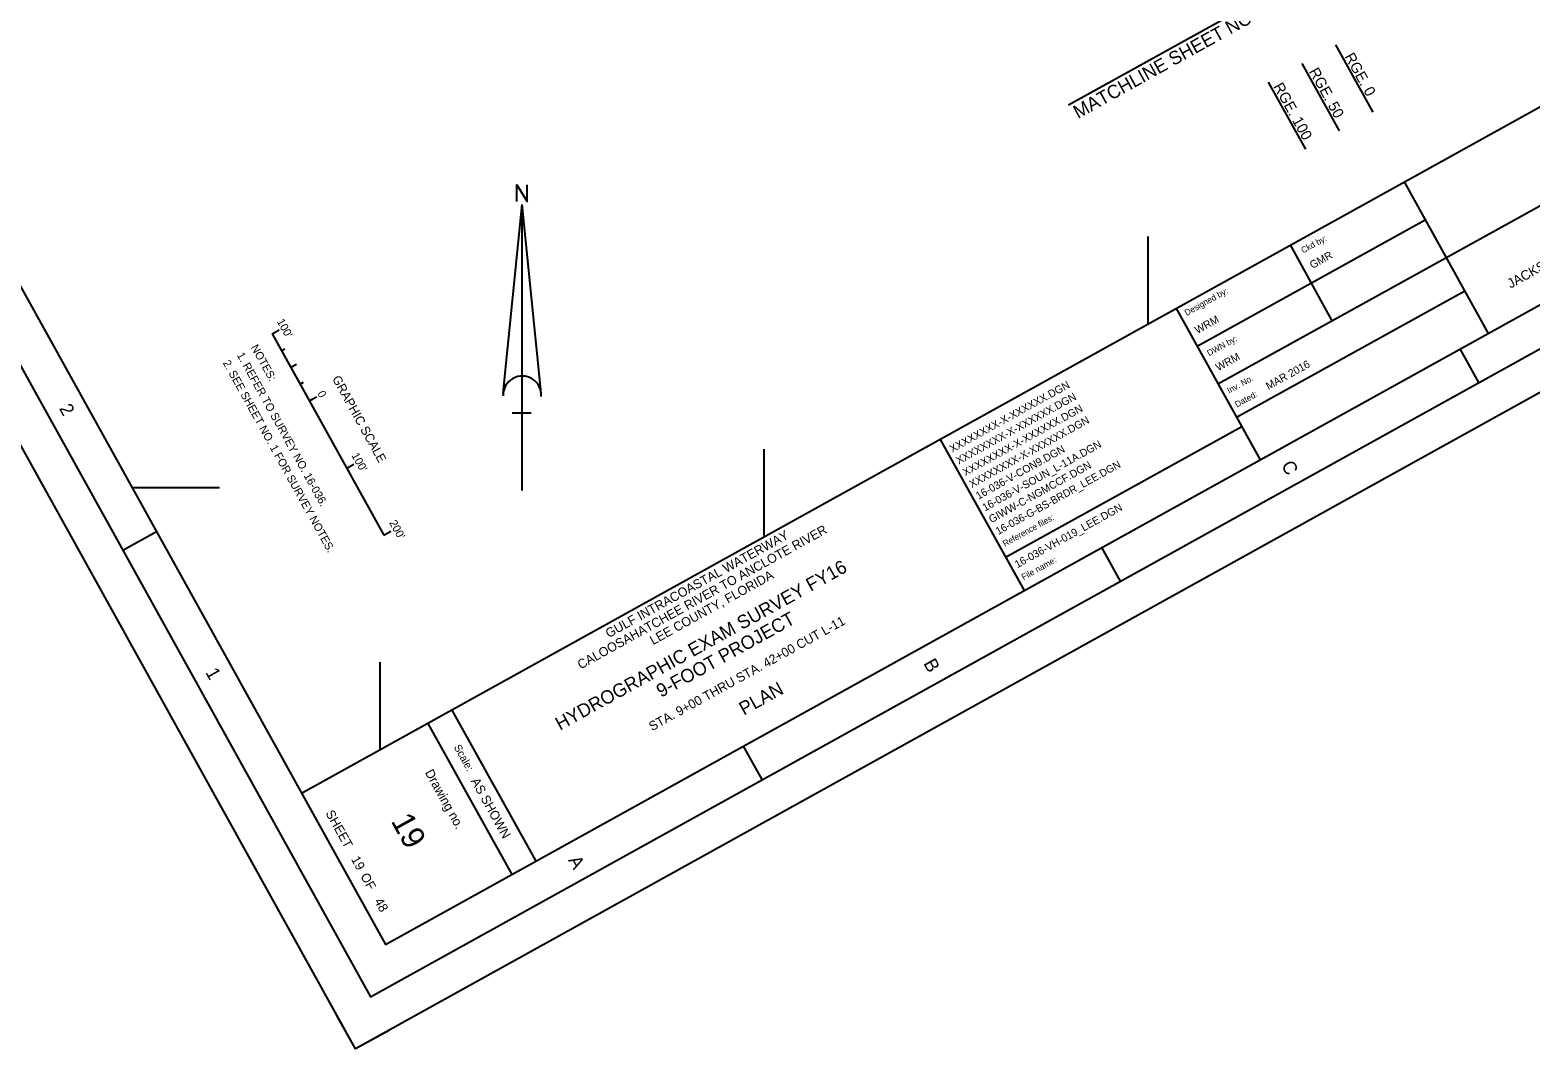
# Model space of a CAD drawing. Extents: x 602834 to 607941, y 795268 to 800765.
# Drawn here: x 604544 to 606498, y 795268 to 796596 of the extents above; entities that cross this region are included whole.
import ezdxf

# ---------------------------------------------------------------- set-up
doc = ezdxf.new("R2010")
doc.units = 0
for name, color, linetype in [('G-ANNO-NPLT', 7, 'Continuous'), ('G-ANNO-TEXT-DRWG', 7, 'Continuous'), ('G-ANNO-TEXT-PROJ', 7, 'Continuous'), ('G-ANNO-TEXT-TTLB', 7, 'Continuous'), ('G-ANNO-TTLB', 7, 'Continuous'), ('V-ALGN-TEXT', 7, 'Continuous'), ('V-ANNO-MATC', 7, 'Continuous'), ('V-ANNO-MATC-IDEN', 7, 'Continuous'), ('V-ANNO-NOTE', 7, 'Continuous'), ('V-ANNO-SYMB', 7, 'Continuous'), ('V-TOPO-COOR-STAT', 7, 'Continuous')]:
    doc.layers.add(name, color=color, linetype=linetype)

msp = doc.modelspace()

# ---------------------------------------------------------------- linework, layer by layer
at = {"layer": 'G-ANNO-NPLT'}
msp.add_lwpolyline([(605807.9, 800765.3), (607941.3, 796917.1), (604967.7, 795268.6), (602834.3, 799116.7)], close=True, dxfattribs=at)
msp.add_lwpolyline([(605011.5, 795292.7), (604967.8, 795268.5), (604943.5, 795312.2)], dxfattribs=at)
at = {"layer": 'G-ANNO-TTLB'}
for p, q in [((607696.2, 797152.9), (604897.6, 795601.3)), ((606090.7, 796134.9), (606842.7, 796551.1)), ((606333.1, 796398.1), (606442.6, 796200.6)), ((606063.6, 796183.8), (606360.7, 796348.3)), ((606184.6, 796315.7), (606239.2, 796217.1)), ((606412.1, 796255.7), (606115, 796091)), ((606035.8, 796233.7), (606145.5, 796035.9)), ((606430.2, 796136.5), (606405.9, 796180.3)), ((606121.6, 796079), (605814.3, 795908.6)), ((605729.1, 796062.3), (605838.2, 795865.5)), ((604664.8, 795918.1), (604708.5, 795942.4)), ((605963.8, 795877.9), (605939.5, 795921.7)), ((605093.3, 795709.8), (605202.4, 795513)), ((605062.1, 795692.5), (605171.2, 795495.7)), ((605497.3, 795619.4), (605473.1, 795663.1))]:
    msp.add_line(p, q, dxfattribs=at)
for points in [[(602902.3, 799097.2), (604987.2, 795336.5), (607873.3, 796936.6), (605788.4, 800697.3)], [(607805.4, 796956.1), (605805.3, 800563.7), (603006.6, 799012.2), (605006.7, 795404.5)]]:
    msp.add_lwpolyline(points, close=True, dxfattribs=at)
at = {"layer": 'V-ALGN-TEXT'}
for p, q in [((606243.7, 796576.2), (606292.2, 796488.8)), ((606200, 796552), (606248.5, 796464.5)), ((606156.2, 796527.7), (606204.7, 796440.3))]:
    msp.add_line(p, q, dxfattribs=at)
at = {"layer": 'V-ANNO-MATC'}
msp.add_line((606406.8, 796781), (605896, 796497.8), dxfattribs=at)
at = {"layer": 'V-ANNO-NOTE'}
for p, q in [((604859.4, 796200.1), (604868.5, 796205.2)), ((604859.4, 796200.1), (605004.8, 795937.7)), ((604871.5, 796178.2), (604875.7, 796180.6)), ((604883.6, 796156.4), (604891.1, 796160.5)), ((604895.7, 796134.5), (604899.9, 796136.8)), ((604907.9, 796112.7), (604917, 796117.7)), ((604907.9, 796112.7), (604917, 796117.7)), ((604907.9, 796112.7), (604912.2, 796115.1)), ((604956.4, 796025.2), (604965.5, 796030.3)), ((605004.8, 795937.7), (605014, 795942.8))]:
    msp.add_line(p, q, dxfattribs=at)
at = {"layer": 'V-ANNO-SYMB'}
for p, q in [((605160.2, 796122.7), (605184.9, 796368.4)), ((605184.9, 795996.1), (605184.9, 796368.4)), ((605209.6, 796122.7), (605184.9, 796368.4)), ((605196.7, 796096.7), (605171.8, 796096.7))]:
    msp.add_line(p, q, dxfattribs=at)
msp.add_lwpolyline([(605178, 796372.4), (605178, 796394.1), (605191.5, 796372.4), (605191.5, 796394.1)], dxfattribs=at)
msp.add_arc((605184.9, 796120.2), 24.8, 355.2984, 182.0673, dxfattribs=at)
at = {"layer": 'V-TOPO-COOR-STAT'}
for p, q in [((606000, 796212.5), (606000, 796326.8)), ((605500, 795935.3), (605500, 796049.6)), ((604676.6, 796000), (604790.9, 796000)), ((605000, 795658.1), (605000, 795772.4))]:
    msp.add_line(p, q, dxfattribs=at)

# ---------------------------------------------------------------- texts
at = {"layer": 'G-ANNO-TEXT-DRWG'}
for s, height, rotation, p in [('GMR', 10, 29.0039, (606213.7, 796284.4)), ('WRM', 10, 29.0039, (606064, 796199.6)), ('WRM', 10, 29.0039, (606091.2, 796151.1)), ('XXXXXXXX-X-XXXXXX.DGN', 10, 29.0039, (605744.8, 796045)), ('XXXXXXXX-X-XXXXXX.DGN', 10, 29.0039, (605753.3, 796029.7)), ('XXXXXXXX-X-XXXXXX.DGN', 10, 29.0039, (605761.8, 796014.4)), ('XXXXXXXX-X-XXXXXX.DGN', 10, 29.0039, (605770.3, 795999.1)), ('16-036-V-CON9.DGN', 10, 29.0039, (605778.8, 795983.8)), ('16-036-V-SOUN_L-11A.DGN', 10, 29.0039, (605787.3, 795968.5)), ('GIWW-C-NGMCCF.DGN', 10, 29.0039, (605795.7, 795953.2)), ('16-036-VH-019_LEE.DGN', 10, 29.0039, (605829.5, 795894.5)), ('STA. 9+00 THRU STA. 42+00 CUT L-11', 12, 29.0039, (605353.9, 795682.3)), ('PLAN', 17.5, 29.0039, (605473.4, 795702.6)), ('19', 30, 299.0039, (605013.3, 795565.5)), (' 19          48', 12, 299.0039, (604959.5, 795519.6))]:
    msp.add_text(s, height=height, rotation=rotation, dxfattribs=at).set_placement(p)
at = {"layer": 'G-ANNO-TEXT-PROJ'}
for s, height, p in [('MAR 2016', 10, (606156.4, 796126.8)), ('16-036-G-BS-BRDR_LEE.DGN', 9.8, (605804.7, 795937.9)), ('CALOOSAHATCHEE RIVER TO ANCLOTE RIVER', 12, (605261, 795762.7)), ('GULF INTRACOASTAL WATERWAY', 12, (605297.5, 795803.5)), ('HYDROGRAPHIC EXAM SURVEY FY16', 17.5, (605234.1, 795682.9)), ('LEE COUNTY, FLORIDA', 12, (605355.2, 795794.4)), ('9-FOOT PROJECT', 17.5, (605365.6, 795725.8))]:
    msp.add_text(s, height=height, rotation=29.0039, dxfattribs=at).set_placement(p)
at = {"layer": 'G-ANNO-TEXT-TTLB'}
for s, height, rotation, p in [('JACKSONVILLE DISTRICT, CORPS OF ENGINEERS', 12.5, 29.0039, (606471.8, 796258.7)), ('Ckd by:', 8, 29.0039, (606201.6, 796304.5)), ('Designed by:', 8, 29.0039, (606050, 796223.2)), ('DWN by:', 8, 29.0039, (606079.2, 796170.6)), ('Inv. No.', 8, 29.0039, (606105.3, 796121.9)), ('Dated:', 8, 29.0039, (606115.5, 796103.8)), ('Reference files:', 8, 29.0039, (605813.3, 795922.5)), ('File name:', 8, 29.0039, (605837.7, 795878.9)), ('Scale:', 10, 299.0039, (605095.5, 795661.7)), ('Drawing no.', 12, 299.0039, (605057.8, 795628.6)), ('AS SHOWN', 12, 299.0039, (605117.7, 795617.6)), ('SHEET         OF', 12, 299.0039, (604928.4, 795575.6))]:
    msp.add_text(s, height=height, rotation=rotation, dxfattribs=at).set_placement(p)
at = {"layer": 'G-ANNO-TTLB'}
for s, p in [('2', (604581.4, 796102.9)), ('C', (606172.6, 796028.9)), ('B', (605706.8, 795770.9)), ('1', (604772, 795759.1)), ('A', (605244.4, 795514.5))]:
    msp.add_text(s, height=17.5, rotation=299.0039, dxfattribs=at).set_placement(p)
at = {"layer": 'V-ALGN-TEXT'}
for s, p in [('RGE. 0', (606255.1, 796561.3)), ('RGE. 50', (606208.8, 796541.8)), ('RGE. 100', (606162.4, 796522.3))]:
    msp.add_text(s, height=13.92, rotation=299.0039, dxfattribs=at).set_placement(p)
at = {"layer": 'V-ANNO-MATC-IDEN'}
msp.add_text('MATCHLINE SHEET NO. 018 LEE STA. 9+00', height=17.52, rotation=29.0039, dxfattribs=at).set_placement((605908.5, 796479.7))
at = {"layer": 'V-ANNO-NOTE'}
for s, height, p in [("100'", 10.42, (604865, 796216.2)), ('NOTES:', 10.42, (604831.2, 796182.5)), ('2. SEE SHEET NO. 1 FOR SURVEY NOTES.', 10.416, (604794.7, 796162.3)), ('1. REFER TO SURVEY NO. 16-036.', 10.416, (604812.9, 796172.4)), ('GRAPHIC SCALE', 11.666, (604937, 796141.6)), ('0', 10.4, (604917.8, 796122.4)), ("100'", 10.42, (604962.2, 796041.7)), ("200'", 10.42, (605011.4, 795954))]:
    msp.add_text(s, height=height, rotation=299.0039, dxfattribs=at).set_placement(p)

doc.saveas('drawing.dxf')
